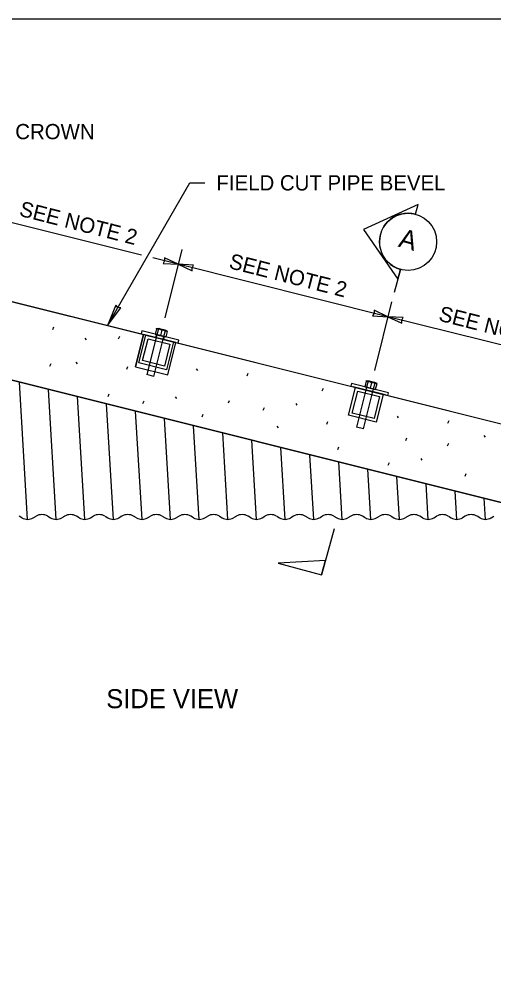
# Model space of a CAD drawing. Extents: x 99862 to 103151, y 100000 to 102076.
# Drawn here: x 101342 to 101840, y 101073 to 102076 of the extents above; entities that cross this region are included whole.
import ezdxf

# ---------------------------------------------------------------- set-up
doc = ezdxf.new("R2010")
doc.units = 0
for name, color, linetype in [('Level 1', 7, 'Continuous'), ('Level 13', 7, 'Continuous'), ('Level 15', 7, 'Continuous'), ('Level 17', 7, 'Continuous'), ('Level 20', 7, 'Continuous'), ('Level 9', 7, 'Continuous')]:
    doc.layers.add(name, color=color, linetype=linetype)

msp = doc.modelspace()

# ---------------------------------------------------------------- linework, layer by layer
at = {"layer": 'Level 1'}
for p, q in [((100938.1, 101796.1), (101898.1, 101556.1)), ((101267.5, 101796.1), (101472.6, 101744.8)), ((101267.9, 101796.1), (101472.7, 101744.9)), ((101472.7, 101744.9), (101464.2, 101711)), ((101464.2, 101711), (101472.6, 101744.8)), ((101467.8, 101715.2), (101475.1, 101744.3)), ((101471, 101748.6), (101470.2, 101745.5)), ((101470.2, 101745.5), (101509, 101735.8)), ((101509.8, 101738.9), (101471, 101748.6)), ((101472.6, 101744.8), (101472.7, 101744.9)), ((101506.6, 101736.4), (101472.7, 101744.9)), ((101475.1, 101744.3), (101504.2, 101737.1)), ((101486.2, 101744.8), (101485.4, 101741.8)), ((101493.9, 101739.6), (101485.4, 101741.8)), ((101486.8, 101744.6), (101486.2, 101744.8)), ((101493.9, 101739.6), (101494.6, 101742.7)), ((101494.6, 101742.7), (101494, 101742.8)), ((101471.6, 101717.5), (101477.4, 101740.5)), ((101477.4, 101740.5), (101500.4, 101734.8)), ((101500.4, 101734.8), (101494.6, 101711.7)), ((101504.2, 101737.1), (101496.9, 101708)), ((101498.1, 101702.5), (101506.6, 101736.4)), ((101506.6, 101736.4), (101692.5, 101690)), ((101509, 101735.8), (101509.8, 101738.9)), ((101464.2, 101711), (101498.1, 101702.5)), ((101496.9, 101708), (101467.8, 101715.2)), ((101494.6, 101711.7), (101471.6, 101717.5)), ((101351.1, 101551.1), (101342.5, 101695)), ((101690.8, 101693.6), (101690.1, 101690.6)), ((101729.6, 101683.9), (101690.8, 101693.6)), ((101381.1, 101551.1), (101372.9, 101687.4)), ((101687.6, 101660.3), (101694.9, 101689.4)), ((101690.1, 101690.6), (101728.9, 101680.9)), ((101691.4, 101662.5), (101697.2, 101685.6)), ((101726.5, 101681.5), (101692.5, 101690)), ((101694.9, 101689.4), (101724, 101682.1)), ((101697.2, 101685.6), (101720.2, 101679.8)), ((101724, 101682.1), (101716.7, 101653)), ((101726.4, 101681.2), (101726.5, 101681.5)), ((101726.5, 101681.5), (101912.3, 101635)), ((101728.9, 101680.9), (101729.6, 101683.9)), ((101411.1, 101551.1), (101403.4, 101679.8)), ((101441.1, 101551.1), (101433.9, 101672.2)), ((101720.2, 101679.8), (101714.5, 101656.8)), ((101471.1, 101551.1), (101464.3, 101664.6)), ((101714.5, 101656.8), (101691.4, 101662.5)), ((101501.1, 101551.1), (101494.8, 101656.9)), ((101716.7, 101653), (101687.6, 101660.3)), ((101531.1, 101551.1), (101525.2, 101649.3)), ((101561.1, 101551.1), (101555.7, 101641.7)), ((101591.1, 101551.1), (101586.1, 101634.1)), ((101621.1, 101551.1), (101616.6, 101626.5)), ((101651.1, 101551.1), (101647.1, 101618.9)), ((101681.1, 101551.1), (101677.5, 101611.3)), ((101711.1, 101551.1), (101708, 101603.6)), ((101741.1, 101551.1), (101738.4, 101596)), ((101771.1, 101551.1), (101768.9, 101588.4)), ((101801.1, 101551.1), (101799.3, 101580.8)), ((101831.1, 101551.1), (101829.8, 101573.2)), ((101345.2, 101552.7), (101342.3, 101554.4)), ((101357, 101552.7), (101360, 101554.4)), ((101372.3, 101554.4), (101375.2, 101552.7)), ((101390, 101554.4), (101387, 101552.7)), ((101405.2, 101552.7), (101402.3, 101554.4)), ((101417, 101552.7), (101420, 101554.4)), ((101432.3, 101554.4), (101435.2, 101552.7)), ((101450, 101554.4), (101447, 101552.7)), ((101465.2, 101552.7), (101462.3, 101554.4)), ((101477, 101552.7), (101480, 101554.4)), ((101492.3, 101554.4), (101495.2, 101552.7)), ((101510, 101554.4), (101507, 101552.7)), ((101525.2, 101552.7), (101522.3, 101554.4)), ((101537, 101552.7), (101540, 101554.4)), ((101552.3, 101554.4), (101555.2, 101552.7)), ((101570, 101554.4), (101567, 101552.7)), ((101585.2, 101552.7), (101582.3, 101554.4)), ((101597, 101552.7), (101600, 101554.4)), ((101612.3, 101554.4), (101615.2, 101552.7)), ((101630, 101554.4), (101627, 101552.7)), ((101645.2, 101552.7), (101642.3, 101554.4)), ((101657, 101552.7), (101660, 101554.4)), ((101672.3, 101554.4), (101675.2, 101552.7)), ((101690, 101554.4), (101687, 101552.7)), ((101705.2, 101552.7), (101702.3, 101554.4)), ((101717, 101552.7), (101720, 101554.4)), ((101732.3, 101554.4), (101735.2, 101552.7)), ((101750, 101554.4), (101747, 101552.7)), ((101765.2, 101552.7), (101762.3, 101554.4)), ((101777, 101552.7), (101780, 101554.4)), ((101792.3, 101554.4), (101795.2, 101552.7)), ((101810, 101554.4), (101807, 101552.7)), ((101825.2, 101552.7), (101822.3, 101554.4)), ((101837, 101552.7), (101840, 101554.4))]:
    msp.add_line(p, q, dxfattribs=at)
msp.add_lwpolyline([(99862, 99999.5), (103151, 99999.5), (103151, 102075.5), (99862, 102075.5)], close=True, dxfattribs=at)
for centre, start, end in [((101351.1, 101563.1), 240.6871, 270), ((101351.1, 101563.1), 270, 299.3129), ((101366.1, 101544.1), 59.2401, 120.7599), ((101381.1, 101563.1), 240.6871, 270), ((101381.1, 101563.1), 270, 299.3129), ((101396.1, 101544.1), 59.2401, 120.7599), ((101411.1, 101563.1), 240.6871, 270), ((101411.1, 101563.1), 270, 299.3129), ((101426.1, 101544.1), 59.2401, 120.7599), ((101441.1, 101563.1), 240.6871, 270), ((101441.1, 101563.1), 270, 299.3129), ((101456.1, 101544.1), 59.2401, 120.7599), ((101471.1, 101563.1), 240.6871, 270), ((101471.1, 101563.1), 270, 299.3129), ((101486.1, 101544.1), 59.2401, 120.7599), ((101501.1, 101563.1), 240.6871, 270), ((101501.1, 101563.1), 270, 299.3129), ((101516.1, 101544.1), 59.2401, 120.7599), ((101531.1, 101563.1), 240.6871, 270), ((101531.1, 101563.1), 270, 299.3129), ((101546.1, 101544.1), 59.2401, 120.7599), ((101561.1, 101563.1), 240.6871, 270), ((101561.1, 101563.1), 270, 299.3129), ((101576.1, 101544.1), 59.2401, 120.7599), ((101591.1, 101563.1), 240.6871, 270), ((101591.1, 101563.1), 270, 299.3129), ((101606.1, 101544.1), 59.2401, 120.7599), ((101621.1, 101563.1), 240.6871, 270), ((101621.1, 101563.1), 270, 299.3129), ((101636.1, 101544.1), 59.2401, 120.7599), ((101651.1, 101563.1), 240.6871, 270), ((101651.1, 101563.1), 270, 299.3129), ((101666.1, 101544.1), 59.2401, 120.7599), ((101681.1, 101563.1), 240.6871, 270), ((101681.1, 101563.1), 270, 299.3129), ((101696.1, 101544.1), 59.2401, 120.7599), ((101711.1, 101563.1), 240.6871, 270), ((101711.1, 101563.1), 270, 299.3129), ((101726.1, 101544.1), 59.2401, 120.7599), ((101741.1, 101563.1), 240.6871, 270), ((101741.1, 101563.1), 270, 299.3129), ((101756.1, 101544.1), 59.2401, 120.7599), ((101771.1, 101563.1), 240.6871, 270), ((101771.1, 101563.1), 270, 299.3129), ((101786.1, 101544.1), 59.2401, 120.7599), ((101801.1, 101563.1), 240.6871, 270), ((101801.1, 101563.1), 270, 299.3129), ((101816.1, 101544.1), 59.2401, 120.7599), ((101831.1, 101563.1), 240.6871, 270), ((101831.1, 101563.1), 270, 299.3129)]:
    msp.add_arc(centre, 12, start, end, dxfattribs=at)
at = {"layer": 'Level 13'}
for p, q in [((100899.3, 101888.3), (102226.1, 101556.6)), ((102146.1, 101494.1), (100879.9, 101810.7))]:
    msp.add_line(p, q, dxfattribs=at)
at = {"layer": 'Level 15'}
for p, q in [((101434.8, 101754.4), (101521.1, 101903.9)), ((101521.1, 101903.9), (101537.1, 101903.9)), ((101470.7, 101828.1), (101289.3, 101873.5)), ((101513, 101834), (101495, 101762.2)), ((101509.1, 101818.5), (101482.3, 101825.2)), ((101728.9, 101763.5), (101509.1, 101818.5)), ((101732.8, 101779.1), (101714.9, 101707.3)), ((101948.8, 101708.6), (101728.9, 101763.5))]:
    msp.add_line(p, q, dxfattribs=at)
for points in [[(101509.1, 101818.5), (101494.6, 101825.3), (101494.5, 101822.1), (101493.1, 101819.3)], [(101509.1, 101818.5), (101523.6, 101811.7), (101523.6, 101814.9), (101525.1, 101817.7)], [(101434.8, 101754.4), (101448.8, 101772.7), (101445.7, 101773.3), (101443.6, 101775.7)], [(101728.9, 101763.5), (101714.4, 101770.4), (101714.4, 101767.2), (101712.9, 101764.4)], [(101728.9, 101763.5), (101743.4, 101756.7), (101743.5, 101759.9), (101744.9, 101762.7)]]:
    msp.add_lwpolyline(points, close=True, dxfattribs=at)
at = {"layer": 'Level 17'}
for p, q in [((101377.6, 101750.3), (101378.8, 101753.1)), ((101411.2, 101741.2), (101412.4, 101739.4)), ((101446.5, 101740.5), (101447.8, 101743.3)), ((101374.6, 101711.6), (101375.9, 101714.4)), ((101401.8, 101715.9), (101403, 101714)), ((101455, 101708.6), (101456.2, 101711.4)), ((101528, 101708.9), (101529.2, 101707)), ((101581.2, 101701.7), (101582.4, 101704.5)), ((101435.5, 101680), (101436.7, 101682.8)), ((101660.1, 101685.8), (101661.5, 101688.6)), ((101471.9, 101672.4), (101473.2, 101675.2)), ((101506, 101679.5), (101507.2, 101677.7)), ((101561.7, 101673.1), (101562.9, 101675.8)), ((101632.2, 101672.5), (101633.4, 101670.7)), ((101534, 101658.5), (101535.3, 101661.3)), ((101598.1, 101665.5), (101599.4, 101668.2)), ((101664.7, 101651), (101666, 101653.8)), ((101738.7, 101659.2), (101739.8, 101657.4)), ((101791.8, 101652), (101793, 101654.8)), ((101612.5, 101648.9), (101613.7, 101647.1)), ((101747.6, 101633.7), (101748.8, 101636.5)), ((101791.3, 101628.2), (101792.6, 101631)), ((101829.5, 101638.9), (101830.7, 101637.1)), ((101676.4, 101624.4), (101677.6, 101627.1)), ((101729.3, 101607.8), (101730.5, 101610.6)), ((101763.4, 101614.9), (101764.5, 101613.1)), ((101809.8, 101596.3), (101811, 101599.1))]:
    msp.add_line(p, q, dxfattribs=at)
at = {"layer": 'Level 9'}
for p, q in [((101760.6, 101881.3), (101703.2, 101854.8)), ((101757.8, 101871), (101760.6, 101881.3)), ((101703.2, 101854.8), (101739.3, 101802.9)), ((101742.1, 101813.1), (101735.5, 101789)), ((101739.3, 101802.9), (101742.1, 101813.1)), ((101486.4, 101751), (101484.9, 101745.1)), ((101486.5, 101751.5), (101489.2, 101750.8)), ((101488.4, 101751), (101486.8, 101744.6)), ((101488.4, 101751), (101486.8, 101744.6)), ((101489.4, 101751.3), (101488.4, 101751)), ((101489.4, 101751.3), (101494.9, 101749.9)), ((101486.8, 101744.6), (101476.3, 101702.8)), ((101483.6, 101701), (101494, 101742.8)), ((101484.9, 101745.1), (101490.4, 101743.7)), ((101486.8, 101744.6), (101494, 101742.8)), ((101489.4, 101750.7), (101489.2, 101750.8)), ((101489.2, 101750.8), (101489.4, 101750.7)), ((101489.4, 101750.7), (101494.6, 101749.4)), ((101491.9, 101749.6), (101490.4, 101743.7)), ((101490.4, 101743.7), (101495.9, 101742.4)), ((101494, 101742.8), (101495.6, 101749.2)), ((101494, 101742.8), (101495.6, 101749.2)), ((101494.8, 101749.4), (101494.6, 101749.4)), ((101494.6, 101749.4), (101494.8, 101749.4)), ((101494.8, 101749.4), (101497.4, 101748.7)), ((101495.6, 101749.2), (101494.9, 101749.9)), ((101497.3, 101748.2), (101495.9, 101742.4)), ((101483.6, 101701), (101476.3, 101702.8)), ((101706.2, 101696), (101704.8, 101690.1)), ((101706.4, 101696.5), (101709, 101695.8)), ((101708.2, 101696), (101706.6, 101689.7)), ((101708.2, 101696), (101706.6, 101689.7)), ((101709.2, 101696.3), (101708.2, 101696)), ((101709.2, 101695.8), (101709, 101695.8)), ((101709, 101695.8), (101709.2, 101695.8)), ((101709.2, 101696.3), (101714.7, 101694.9)), ((101709.2, 101695.8), (101714.4, 101694.5)), ((101711.7, 101694.6), (101710.2, 101688.8)), ((101713.9, 101687.9), (101715.5, 101694.2)), ((101713.9, 101687.9), (101715.5, 101694.2)), ((101714.7, 101694.4), (101714.4, 101694.5)), ((101714.4, 101694.5), (101714.7, 101694.4)), ((101715.4, 101694.3), (101714.7, 101694.9)), ((101714.7, 101694.4), (101717.3, 101693.8)), ((101717.2, 101693.3), (101715.7, 101687.4)), ((101706.6, 101689.7), (101696.1, 101647.8)), ((101703.4, 101646), (101713.9, 101687.9)), ((101704.8, 101690.1), (101710.2, 101688.8)), ((101706.6, 101689.7), (101713.9, 101687.9)), ((101710.2, 101688.8), (101715.7, 101687.4)), ((101703.4, 101646), (101696.1, 101647.8)), ((101672.4, 101541.1), (101659.3, 101492.9))]:
    msp.add_line(p, q, dxfattribs=at)
msp.add_lwpolyline([(101663.3, 101507.9), (101614, 101505.2), (101659.3, 101492.9)], close=True, dxfattribs=at)
msp.add_circle((101750, 101842.1), 30, dxfattribs=at)
msp.add_arc((101750, 101842.1), 30, 74.8053, 254.8097, dxfattribs=at)
for points, degree in [([(101486.5, 101751.5), (101486.5, 101751.5), (101486.5, 101751.4), (101486.5, 101751.4), (101486.5, 101751.4), (101486.5, 101751.2), (101486.4, 101751)], 3), ([(101486.4, 101751), (101486.4, 101751), (101486.4, 101751.1), (101486.5, 101751.2), (101486.5, 101751.3), (101486.5, 101751.5), (101486.5, 101751.5)], 3), ([(101491.9, 101749.6), (101491, 101750.2), (101490.1, 101750.6), (101489.1, 101750.8), (101488.2, 101751), (101487.3, 101751), (101486.4, 101751)], 3), ([(101486.4, 101751), (101486.4, 101751), (101486.4, 101751), (101486.4, 101751)], 2), ([(101486.4, 101751), (101487.3, 101751), (101488.3, 101751), (101489.2, 101750.8)], 2), ([(101495.6, 101749.2), (101495.6, 101749.2), (101495.6, 101749.2), (101495.6, 101749.2), (101495.5, 101749.2), (101495.4, 101749.2), (101495.2, 101749.3), (101495, 101749.3), (101494.8, 101749.4), (101494.5, 101749.5), (101494.2, 101749.6), (101493.8, 101749.6), (101493.4, 101749.7), (101493.1, 101749.8), (101492.7, 101749.9), (101492.3, 101750), (101491.8, 101750.1), (101491.4, 101750.2), (101491, 101750.3), (101490.6, 101750.4), (101490.3, 101750.5), (101489.9, 101750.6), (101489.6, 101750.7), (101489.3, 101750.8), (101489.1, 101750.8), (101488.8, 101750.9), (101488.6, 101750.9), (101488.5, 101751), (101488.4, 101751), (101488.4, 101751), (101488.4, 101751)], 3), ([(101488.4, 101751), (101488.4, 101751), (101488.4, 101751), (101488.4, 101751), (101488.4, 101751), (101488.5, 101751), (101488.6, 101750.9), (101488.8, 101750.9), (101489, 101750.8), (101489.3, 101750.8), (101489.5, 101750.7), (101489.8, 101750.6), (101490.2, 101750.5), (101490.6, 101750.4), (101490.9, 101750.3), (101491.3, 101750.2), (101491.7, 101750.1), (101492.2, 101750), (101492.6, 101749.9), (101493, 101749.8), (101493.4, 101749.7), (101493.7, 101749.7), (101494, 101749.6), (101494.2, 101749.5), (101494.4, 101749.5)], 3), ([(101488.6, 101750.9), (101488.6, 101750.9), (101488.7, 101750.9), (101488.7, 101750.9), (101488.9, 101750.9), (101489.2, 101750.8), (101489.5, 101750.7), (101489.7, 101750.7), (101490.1, 101750.6), (101490.5, 101750.5), (101490.8, 101750.4), (101491.2, 101750.3), (101491.6, 101750.2), (101492, 101750.1), (101492.5, 101750), (101492.9, 101749.9), (101493.3, 101749.8), (101493.6, 101749.7), (101494, 101749.6), (101494.3, 101749.5), (101494.6, 101749.4), (101494.9, 101749.4), (101495.1, 101749.3), (101495.3, 101749.3), (101495.4, 101749.2)], 3), ([(101495.4, 101749.2), (101495.4, 101749.2), (101495.4, 101749.2), (101495.4, 101749.2), (101495.3, 101749.3), (101495, 101749.3), (101494.8, 101749.4), (101494.5, 101749.5), (101494.2, 101749.5), (101493.9, 101749.6), (101493.5, 101749.7), (101493.1, 101749.8), (101492.7, 101749.9), (101492.3, 101750), (101491.9, 101750.1), (101491.5, 101750.2), (101491.1, 101750.3), (101490.7, 101750.4), (101490.3, 101750.5), (101490.1, 101750.6), (101489.9, 101750.6), (101489.7, 101750.7), (101489.4, 101750.7), (101489.1, 101750.8), (101488.9, 101750.9), (101488.8, 101750.9), (101488.6, 101750.9), (101488.6, 101750.9)], 3), ([(101489.4, 101750.7), (101489.4, 101750.7), (101489.4, 101750.7), (101489.4, 101750.7), (101490.3, 101750.5), (101491.1, 101750.1), (101491.9, 101749.6)], 3), ([(101494.7, 101749.4), (101494.6, 101749.4), (101494.6, 101749.4), (101494.5, 101749.5), (101493.7, 101749.6), (101492.8, 101749.7), (101491.9, 101749.6)], 3), ([(101491.9, 101749.6), (101492.8, 101749.7), (101493.7, 101749.6), (101494.6, 101749.4)], 2), ([(101494.4, 101749.5), (101494.7, 101749.4), (101494.9, 101749.4), (101495.1, 101749.3), (101495.3, 101749.3), (101495.5, 101749.2), (101495.6, 101749.2), (101495.6, 101749.2), (101495.6, 101749.2), (101495.6, 101749.2)], 3), ([(101497.3, 101748.2), (101496.5, 101748.7), (101495.7, 101749.2), (101494.8, 101749.4)], 2), ([(101494.8, 101749.4), (101494.9, 101749.4), (101494.9, 101749.4), (101494.9, 101749.4), (101495.8, 101749.1), (101496.6, 101748.7), (101497.3, 101748.2)], 3), ([(101497.3, 101748.2), (101497.3, 101748.3), (101497.4, 101748.4), (101497.4, 101748.4), (101497.4, 101748.6), (101497.4, 101748.7), (101497.4, 101748.7)], 3), ([(101706.4, 101696.5), (101706.4, 101696.5), (101706.4, 101696.5), (101706.4, 101696.5), (101706.3, 101696.4), (101706.3, 101696.2), (101706.2, 101696)], 3), ([(101706.2, 101696), (101706.3, 101696.1), (101706.3, 101696.1), (101706.3, 101696.2), (101706.3, 101696.4), (101706.4, 101696.5), (101706.4, 101696.5)], 3), ([(101711.7, 101694.6), (101710.8, 101695.2), (101709.9, 101695.6), (101708.9, 101695.9), (101708, 101696.1), (101707.1, 101696.1), (101706.2, 101696)], 3), ([(101706.2, 101696), (101707.2, 101696.1), (101708.1, 101696), (101709, 101695.8)], 2), ([(101706.2, 101696), (101706.2, 101696), (101706.2, 101696), (101706.2, 101696)], 2), ([(101715.5, 101694.2), (101715.5, 101694.2), (101715.4, 101694.2), (101715.4, 101694.2), (101715.4, 101694.3), (101715.2, 101694.3), (101715, 101694.3), (101714.8, 101694.4), (101714.6, 101694.4), (101714.3, 101694.5), (101714, 101694.6), (101713.6, 101694.7), (101713.3, 101694.8), (101712.9, 101694.9), (101712.5, 101695), (101712.1, 101695.1), (101711.7, 101695.2), (101711.3, 101695.3), (101710.9, 101695.4), (101710.5, 101695.5), (101710.1, 101695.6), (101709.8, 101695.7), (101709.4, 101695.7), (101709.1, 101695.8), (101708.9, 101695.9), (101708.6, 101695.9), (101708.5, 101696), (101708.3, 101696), (101708.2, 101696), (101708.2, 101696), (101708.2, 101696)], 3), ([(101708.2, 101696), (101708.2, 101696), (101708.2, 101696), (101708.2, 101696), (101708.2, 101696), (101708.3, 101696), (101708.4, 101696), (101708.6, 101695.9), (101708.8, 101695.9), (101709.1, 101695.8), (101709.4, 101695.7), (101709.7, 101695.7), (101710, 101695.6), (101710.4, 101695.5), (101710.8, 101695.4), (101711.2, 101695.3), (101711.6, 101695.2), (101712, 101695.1), (101712.4, 101695), (101712.8, 101694.9), (101713.2, 101694.8), (101713.6, 101694.7), (101713.8, 101694.6), (101714, 101694.6), (101714.2, 101694.5)], 3), ([(101708.4, 101696), (101708.4, 101696), (101708.5, 101696), (101708.6, 101695.9), (101708.8, 101695.9), (101709, 101695.8), (101709.3, 101695.8), (101709.6, 101695.7), (101709.9, 101695.6), (101710.3, 101695.5), (101710.7, 101695.4), (101711.1, 101695.3), (101711.5, 101695.2), (101711.9, 101695.1), (101712.3, 101695), (101712.7, 101694.9), (101713.1, 101694.8), (101713.5, 101694.7), (101713.8, 101694.6), (101714.2, 101694.5), (101714.5, 101694.5), (101714.7, 101694.4), (101714.9, 101694.4), (101715.1, 101694.3), (101715.2, 101694.3)], 3), ([(101715.2, 101694.3), (101715.2, 101694.3), (101715.2, 101694.3), (101715.2, 101694.3), (101715.1, 101694.3), (101714.9, 101694.4), (101714.6, 101694.4), (101714.4, 101694.5), (101714, 101694.6), (101713.7, 101694.7), (101713.3, 101694.8), (101712.9, 101694.8), (101712.6, 101694.9), (101712.2, 101695), (101711.7, 101695.2), (101711.3, 101695.3), (101710.9, 101695.4), (101710.5, 101695.5), (101710.2, 101695.5), (101709.9, 101695.6), (101709.7, 101695.7), (101709.5, 101695.7), (101709.2, 101695.8), (101708.9, 101695.9), (101708.7, 101695.9), (101708.6, 101695.9), (101708.5, 101696), (101708.4, 101696)], 3), ([(101709.2, 101695.8), (101709.2, 101695.8), (101709.3, 101695.8), (101709.3, 101695.8), (101710.1, 101695.5), (101710.9, 101695.1), (101711.7, 101694.6)], 3), ([(101714.5, 101694.5), (101714.4, 101694.5), (101714.4, 101694.5), (101714.4, 101694.5), (101713.5, 101694.7), (101712.6, 101694.7), (101711.7, 101694.6)], 3), ([(101711.7, 101694.6), (101712.6, 101694.7), (101713.5, 101694.7), (101714.4, 101694.5)], 2), ([(101714.2, 101694.5), (101714.5, 101694.5), (101714.8, 101694.4), (101715, 101694.3), (101715.2, 101694.3), (101715.3, 101694.3), (101715.4, 101694.2), (101715.4, 101694.2), (101715.5, 101694.2), (101715.5, 101694.2)], 3), ([(101717.2, 101693.3), (101716.4, 101693.8), (101715.5, 101694.2), (101714.6, 101694.4)], 2), ([(101714.7, 101694.4), (101714.7, 101694.4), (101714.7, 101694.4), (101714.7, 101694.4), (101715.6, 101694.2), (101716.4, 101693.8), (101717.2, 101693.3)], 3), ([(101717.2, 101693.3), (101717.2, 101693.4), (101717.2, 101693.4), (101717.2, 101693.5), (101717.2, 101693.6), (101717.3, 101693.8), (101717.3, 101693.8)], 3)]:
    msp.add_open_spline(points, degree=degree, dxfattribs=at)

# ---------------------------------------------------------------- texts
at = {"layer": 'Level 20'}
for s, height, p in [('CULVERT CROWN', 16, (101232.4, 101949.6)), ('FIELD CUT PIPE BEVEL', 16, (101549.1, 101895.9)), ('SIDE VIEW', 20, (101433.6, 101353.1))]:
    msp.add_text(s, height=height, dxfattribs=at).set_placement(p)
for s, height, rotation, p in [('SEE NOTE 2', 16, 345.7755, (101341.5, 101869.5)), ('A', 20, 344.8075, (101739, 101837.2)), ('SEE NOTE 2', 16, 345.7755, (101561.3, 101814.6)), ('SEE NOTE 2', 16, 345.7755, (101781.2, 101759.6))]:
    msp.add_text(s, height=height, rotation=rotation, dxfattribs=at).set_placement(p)

doc.saveas('drawing.dxf')
